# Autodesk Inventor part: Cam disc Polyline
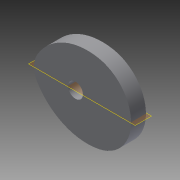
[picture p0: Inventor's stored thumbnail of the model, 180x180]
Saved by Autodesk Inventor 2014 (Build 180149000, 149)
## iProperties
Created: 2008-06
Part Number: Cam disc Polyline
Document SubType Name: Modeling
Designer: tangg
Density: 1 g/cm^3
Mass: 6.8214 g
Surface Area: 30.2978 cm^2
Volume: 6.8214 cm^3
Material: Generic
Appearance: Default
Author: tangg
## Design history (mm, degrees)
sketch "Sketch6"
  geometry: L1 (-27.024, 0)-(35.639, 0) reference; L2 (0, -29.269)-(0, 29.269) reference; C1 r 3.175 at (0, 0); A1 r 10.048 centre (-7.62, 0) between (-16.236, 5.17) and (-16.236, -5.17); A2 r 24.859 centre (5.08, -7.62) between (9.955, 16.756) and (-16.236, 5.17); A3 r 17.088 centre (6.604, 0) between (9.955, -16.756) and (9.955, 16.756); A4 r 10.048 centre (-7.62, 0) between (-16.236, 5.17) and (-16.236, -5.17); A5 r 24.859 centre (5.08, 7.62) between (-16.236, -5.17) and (9.955, -16.756); A6 r 17.088 centre (6.604, 0) between (9.955, -16.756) and (23.692, 0)
  constraints: 13 point on circle, 7 centre point, 5 symmetric about line, 4 tangent, 2 point on line, 1 midpoint, 3 other
  dimensions: "d11" = 7.62 distance from line of L1 A5.centre; "d12" = 5.08 distance from line of L2 A5.centre; "d13" = 6.35 diameter of C1; "d16" = 6.604 distance from line of L2 A3.centre; "d17" = 7.62 distance from line of L2 A1.centre
extrude "Extrusion2" new body sketch "Sketch6" distance "d14" = 6.35; taper "d15" = 0 deg
body "Solid1"
